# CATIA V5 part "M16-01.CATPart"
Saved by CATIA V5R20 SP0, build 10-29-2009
Part number: M16-01
Revision: ANY
Definition: UNKNOWN
Nomenclature: M16-01
Source: Unknown
Bounding box of the stored display mesh (mm): x -8 to 8, y -8 to 8, z 0 to 290
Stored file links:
  C:\Users\Utente\Desktop\IO LAVORO\3D X SITO CF\X 3D SITO CF 27-09-2020\740T\M16-01.CATPart
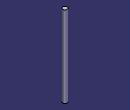
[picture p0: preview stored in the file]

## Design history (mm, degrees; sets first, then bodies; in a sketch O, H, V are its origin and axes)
Body1 "NONE" (main body)
  Solid1: solid without history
